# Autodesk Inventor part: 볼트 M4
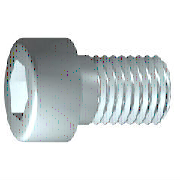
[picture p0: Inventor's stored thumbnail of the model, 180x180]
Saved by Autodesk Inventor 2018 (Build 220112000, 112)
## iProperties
IsCustomPart: 0
Created: 2018-09
Part Number: 볼트 M4
Material: 스테인리스강
Description: 6각머리 태핑 나사
Document SubType Name: Modeling
Standard: KS B 1003
Standards Organization: KS
Language: ko-KR
Size Designation: M 4 x 10
Categories: <MemberInstance><Categories><Category DisplayName="조임쇠" InternalName="e4da775c-781d-43d5-af7c-5136215cf5a6" Mnemonic="FSTN"><Category DisplayName="볼트" InternalN
Density: 8.08 g/cm^3
Mass: 2.09412 g
Surface Area: 3.0572 cm^2
Volume: 0.259174 cm^3
Appearance: 반광택
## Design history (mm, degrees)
sketch "스케치1"
  geometry: L1 (-1, 0)-(10, 0); L2 (10, 0)-(10, 2); L3 (10, 2)-(1.75, 2); L4 (1.75, 2)-(1.32, 2); L5 (1.32, 2)-(0, 2); L6 (0, 2)-(0, 3.5); L7 (0, 3.5)-(-4, 3.5); L8 (-4, 3.5)-(-4, 1.732); L9 (-4, 1.732)-(-2, 1.732); L10 (-2, 1.732)-(-1, 0); L11 (-6.8, 0)-(12.8, 0) reference; L12 (0, -0.7)-(0, 4.2) reference; L13 (1.75, 2)-(0, 2)
  constraints: 22 end point, 6 parallel, 2 collinear, 2 perpendicular, 1 horizontal, 1 point on line
  dimensions: "d1" = 8.25 distance from line of L3.end L2 (= GEL); "d2" = 0.42952 distance of L4.end L3.end (computed from GAL); "d3" = 4 distance between parallel lines of L8 L6 (= KOH); "d4" = 2 distance of L8.end L9.end (= INTI); "d5" = 60 deg angle of L10 L1; "d6" = 4 diameter of L3 L1 (= GD); "d7" = 4 diameter of L5 L1 (= BDM); "d8" = 3.4641 diameter of L9 L1 (= 1.1547 x SW); "d9" = 7 diameter of L7 L1 (= KOD); "d26" = 10 distance between parallel lines of L12 L2 (= NLG)
revolve "본체" sketch "스케치1" stored, may be unused: angle "d10" = 90 deg
sketch "스케치2"
  geometry: L1 (0, -4.9)-(0, 4.9) reference; L2 (-4.9, 0)-(4.9, 0) reference; L3 (1.732, 0)-(0.866, -1.5); L4 (0.866, -1.5)-(-0.866, -1.5); L5 (-0.866, -1.5)-(-1.732, 0); L6 (-1.732, 0)-(-0.866, 1.5); L7 (-0.866, 1.5)-(0.866, 1.5); L8 (0.866, 1.5)-(1.732, 0); 2 further points
  constraints: 12 end point, 1 coincident, 1 horizontal alignment, 1 point on line, 12 other
extrude "슬롯" join sketch "스케치2" stored distance "d11" = 10; taper "d12" = 0 deg
workplane "Work Plane1"
fillet "Fillet2" dims "d30" = 0.1 (= R)
body "Solid1"
fillet "모깎기1" dims "d17" = 0.4 (= RR)
feature "스레드" dims "d13" = 8.25 (= GEL), "d14" = 0
chamfer "모따기1" distance "d15" = 0.42941 (= -0.5 x SPD + 0.5 x GD); stored, may be unused: second distance "d16" = 0.42941 (= GUL), angle "d27" = 45 deg
other parameters: "GD" = 4 (= NND) [user parameter; used in 2 equation terms], "NLG" = 10 [user parameter; used in 1 equation term], "GEL" = 8.25 [user parameter; used in 2 equation terms], "KOD" = 7 [user parameter; used in 1 equation term], "KOH" = 4 [user parameter; used in 1 equation term], "INTI" = 2 [user parameter; used in 1 equation term], "GAL" = 0.42941 (= 0.61345 x PTC) [user parameter; used in 1 equation term], "GUL" = 0.42941 (= 0.61345 x PTC) [user parameter; used in 1 equation term], "BDM" = 4 (= NND) [user parameter; used in 1 equation term], "SW" = 3 [user parameter; used in 2 equation terms], "RR" = 0.4 [user parameter; used in 1 equation term], "SPD" = 3.14117 (= NND - 1.2269 x PTC) [user parameter; used in 1 equation term], "d19" = 0, "d28" = 0, "d29" = 0, "R" = 0.1 [user parameter; used in 1 equation term], "PHH" = 0.2 [user parameter], "GD1" = 3.14117 (= THREADDIA - 1.2269 x PTC) [user parameter], "THREADDIA" = 4 [user parameter; used in 1 equation term], "FAWI" = 45 deg [user parameter], "TPU" = 14.28571 (computed from PTC) [user parameter], "PTC" = 0.7 [user parameter; used in 5 equation terms], "NND" = 4 [user parameter; used in 3 equation terms], "TOA" = 30 deg [user parameter], "E0" = 3.465 (= 1.155 x SW) [user parameter]
